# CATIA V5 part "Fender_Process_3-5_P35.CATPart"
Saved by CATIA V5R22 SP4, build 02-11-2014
Part number: Fender
Bounding box of the stored display mesh (mm): x -800 to 0, y -50.127 to 122.298, z 0 to 580
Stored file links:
  C:\DATA\Car_ASSY\教育モデル\3_SOL\Fender_Process_3-5_P35.CATPart
  C:\DATA\Car_ASSY\教育モデル\3_SOL\Car_Fender.CATPart
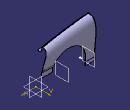
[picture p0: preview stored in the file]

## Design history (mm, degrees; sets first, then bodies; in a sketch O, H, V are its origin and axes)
Set1
  Plane1: type Offset, RefPlane yz-plane, Offset 400, reversed
  Plane2: type Offset, RefPlane Plane1, Offset 400, reversed
Body1 (main body)
Body2
  Sketch1 on yz-plane, origin (0, 0, 0), H (0, 1, 0), V (0, 0, 1)
    point P4 (100, 50)
    point P5 (10, 450)
    spline S1 through (10, 450) (100, 50)
    line L1 (0, 450) -> (10, 450)
    line L2 (0, 0) -> (0, 450)
    line L3 (100, 0) -> (0, 0)
    line L4 (100, 50) -> (100, 0)
    point P6 (100, 50)
    point P7 (10, 450)
    distance P4 L3 = 50
    distance P5 L2 = 10
    distance L4 L2 = 100
    distance L1 H = 450
    coincidence: L2 V, H L3, P4 P6, P7 P5
  Sketch2 on Plane1, origin (-400, 0, 0), H (0, 1, 0), V (0, 0, 1)
    point P4 (100, 50)
    point P5 (10, 530)
    spline S1 through (10, 530) (100, 50)
    line L1 (0, 530) -> (10, 530)
    line L2 (0, 0) -> (0, 530)
    line L3 (100, 0) -> (0, 0)
    line L4 (100, 50) -> (100, 0)
    point P6 (100, 50)
    point P7 (10, 530)
    distance P4 L3 = 50
    distance P5 L2 = 10
    distance L4 L2 = 100
    distance L1 H = 530
    coincidence: L2 V, H L3, P4 P6, P7 P5
  Sketch3 on Plane2, origin (-800, 0, 0), H (0, 1, 0), V (0, 0, 1)
    point P4 (100, 50)
    point P5 (10, 580)
    spline S1 through (10, 580) (100, 50)
    line L1 (0, 580) -> (10, 580)
    line L2 (0, 0) -> (0, 580)
    line L3 (100, 0) -> (0, 0)
    line L4 (100, 50) -> (100, 0)
    point P6 (100, 50)
    point P7 (10, 580)
    distance P4 L3 = 50
    distance P5 L2 = 10
    distance L4 L2 = 100
    distance L1 H = 580
    coincidence: L2 V, H L3, P4 P6, P7 P5
  Loft1: solid, Sections (Sketch1; Sketch2; Sketch3)
  Body3
    Sketch4 on zx-plane, origin (0, 0, 0), H (-1, 0, 0), V (0, 0, 1)
      line L1 (-46.4952, 240) -> (159.0779, 240)
      arc A1 centre (390, 110) radius 265 from (159.0779, 240) to (655, 109.9999) cw
      point P2 (390, 110)
      line L2 (655, 109.9999) -> (655, -30)
      line L3 (-46.4952, 626.6258) -> (850, 626.6258)
      line L4 (850, 626.6258) -> (850, -30)
      line L5 (850, -30) -> (655, -30)
      line L6 (-46.4952, 626.6258) -> (-46.4952, 240)
      radius A1 = 265
      distance P2 H = 110
      distance V P2 = 390
      distance H L1 = 240
      horizontal: L1 H, L3 H, L5 H
      tangency: L2 A1
      vertical: L2 V, L4 V, L6 V
    Pad1: profile Sketch4, direction (0, 1, 0), length 340, mirrored extent
  Intersect1: tool Body3
  Shell1: ExtOffset 0, Face (face of Loft1; face of Loft1; face of Pad1 from Sketch4.A1; face of Pad1 from Sketch4.L1; face of Loft1; face of Loft1), IntOffset 3
  Sketch5 on Plane2, origin (-800, 0, 0), H (0, 1, 0), V (0, 0, 1)
    line L1 (0, 580) -> (0, 545)
    line L2 (-5, 540) -> (-40, 540)
    point P2 (-40, 540)
    reference projected line E1 (10, 580) -> (0, 580)
    reference intersected line E2 (0, 0) -> (0, 580)
    arc A1 centre (-5, 545) radius 5 from (-5, 540) to (0, 545) ccw
    line L3 (-5, 537) -> (-40, 537)
    arc A2 centre (-5, 545) radius 8 from (-5, 537) to (3, 545) ccw
    line L4 (3, 580) -> (3, 545)
    line L5 (-40, 537) -> (-40, 540)
    line L6 (3, 580) -> (0, 580)
    reference projected line E3 (10, 580) -> (0, 580)
    distance E1 L2 = 40
    radius A1 = 5
    distance L1 P2 = 40
    length L5 = 3
    length L6 = 3
    radius A2 = 8
    vertical: L1 V, L4 V, L5 V
    horizontal: L2 H, L6 H, L3 H
    coincidence: L1 E2, L6 E3
    tangency: A1 L2, A1 L1, L4 A2, A2 L3
  Rib1: profile Sketch5, centre curve edge [face of Loft1 | face of Loft1]
  Sketch6 on Plane2, origin (-800, 0, 0), H (0, 1, 0), V (0, 0, 1)
    projected curve E1
    projected line E2 (10, 576.9862) -> (3, 576.9862)
    point P4 (3, 576.9862)
    projected line E3 (3, 576.9862) -> (3, 545)
    projected line E4 (3, 576.9862) -> (3, 399.233)
    point P5 (3, 576.9862)
    projected line E5 (97, 0) -> (97, 50)
    line L1 (97, 0) -> (37, 0)
    line L2 (37, 0) -> (17.9077, 155.4943)
    arc A1 centre (2003, 399.233) radius 2000 from (3, 399.233) to (17.9077, 155.4943) ccw
    angle L1 L2 = 97
    length L1 = 60
    radius A1 = 2000
    horizontal: L1 H
    tangency: A1 E3, A1 L2
    coincidence: P4 P5
  Pad2: profile Sketch6, direction (1, 0, 0), length 10, opposite side length -7
  Sketch7 on yz-plane, origin (0, 0, 0), H (0, 1, 0), V (0, 0, 1)
    projected curve E1
    projected curve E2
    point P1 (103.8705, 240)
    line L1 (100.927, 243) -> (92.1161, 243)
    line L2 (86.1161, 237) -> (86.1161, 160)
    line L3 (86.1161, 160) -> (89.1161, 160)
    line L4 (89.1161, 160) -> (89.1161, 237)
    point P5 (103.8705, 240)
    line L5 (101.1109, 260) -> (104.111, 260)
    point P6 (101.1109, 260)
    point P7 (104.111, 260)
    offset curve E3
    offset curve E4
    line L6 (92.1161, 240) -> (103.8705, 240)
    arc A1 centre (92.1161, 237) radius 3 from (92.1161, 240) to (89.1161, 237) ccw
    arc A2 centre (92.1161, 237) radius 6 from (92.1161, 243) to (86.1161, 237) ccw
    distance L4 L2 = 3
    distance L4 E1 = 15
    distance L1 L6 = 3
    radius A1 = 3
    radius A2 = 6
    distance L6 L3 = 80
    distance L5 L6 = 20
    horizontal: L1 H, L3 H, L5 H, L6 H
    vertical: L2 V, L4 V
    coincidence: P7 E1, E3 P6, P6 L5, P7 L5, P5 P1
    tangency: A1 L6, A1 L4, A2 L1, A2 L2
  Rib2: profile Sketch7, centre curve edge [face of Pad1 from Sketch4.L1 | face of Shell1]
  Body4
    Sketch8 on zx-plane, origin (0, 0, 0), H (-1, 0, 0), V (0, 0, 1)
      point P1 (0, 300)
      line L1 (0, 300) -> (127.0171, 520)
      line L2 (127.0171, 520) -> (-100, 520)
      line L3 (-100, 520) -> (-100, 300)
      line L4 (-100, 300) -> (0, 300)
      angle L1 L4 = 120
      distance L4 H = 300
      coincidence: P1 V
      horizontal: L2 H, L4 H
      vertical: L3 V
    Pad3: profile Sketch8, direction (0, 1, 0), length 220, mirrored extent
  Remove1: tool Body4
  Sketch9 on xy-plane, origin (0, 0, 0), H (1, 0, 0), V (0, 1, 0)
    line L1 (-730, -50.1266) -> (-730, -25)
    arc A1 centre (-725, -25) radius 5 from (-730, -25) to (-720, -25) cw
    point P3 (-725, -25)
    line L2 (-720, -25) -> (-720, -50.1266)
    line L3 (-720, -50.1266) -> (-730, -50.1266)
    reference projected line E1 (-5.7993, -40) -> (-800, -40)
    reference projected line E2 (-800, -40) -> (-800, -5)
    radius A1 = 5
    distance P3 E1 = 15
    distance P3 E2 = 75
    vertical: L1 V, L2 V
    tangency: A1 L1, L2 A1
    horizontal: L3 H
